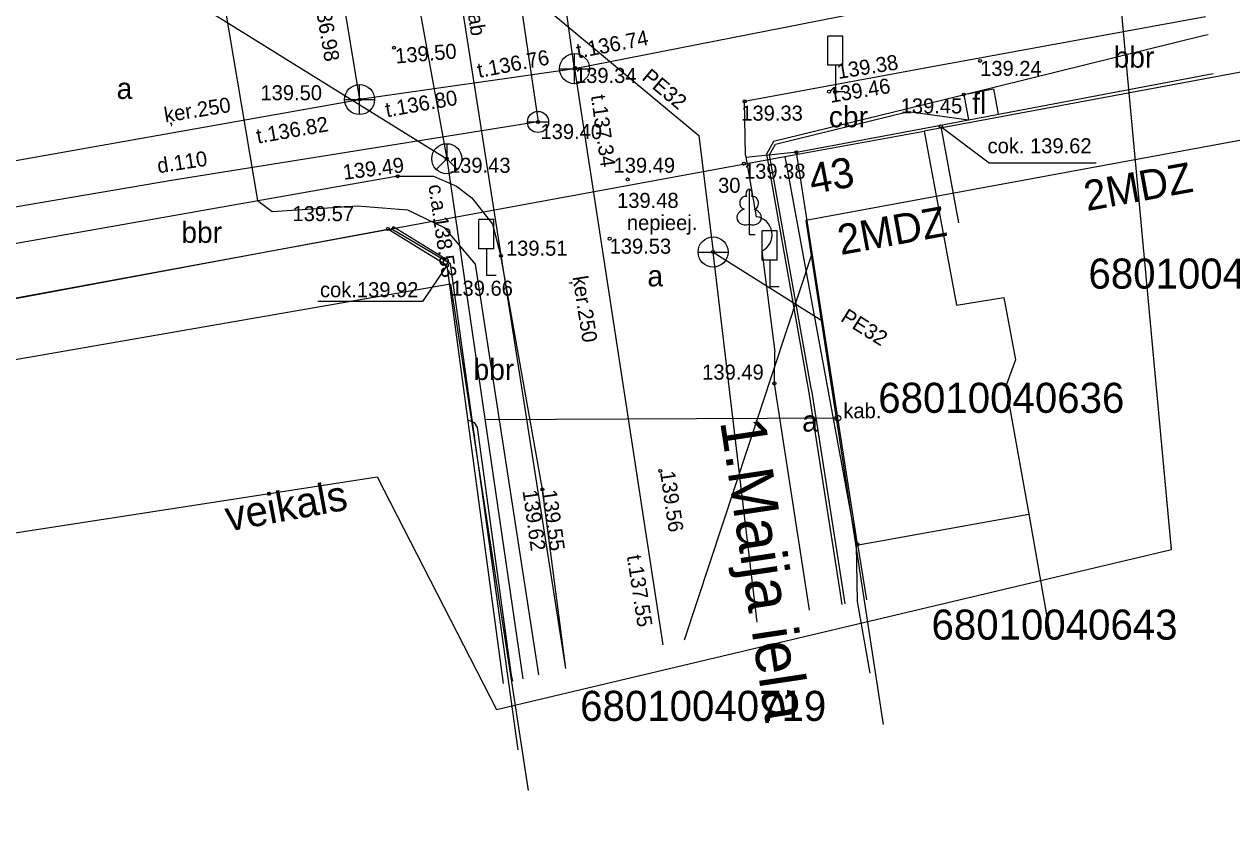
# Model space of a CAD drawing. Extents: x 728492 to 729038, y 272968 to 273171.
# Drawn here: x 728950.66 to 728990.81, y 273100 to 273126.6 of the extents above; entities that cross this region are included whole.
import ezdxf

# ---------------------------------------------------------------- set-up
doc = ezdxf.new("R2010")
doc.units = 0
for name, color, linetype in [('APGR_SARK_####_####_#', 7, 'Continuous'), ('BUVE_BDET_####_####_#', 7, 'Continuous'), ('BUVE_BDET_####_TKST_#', 7, 'Continuous'), ('BUVE_EKAS_####_####_#', 7, 'Continuous'), ('BUVE_EKAS_ADRS_TKST_#', 7, 'Continuous'), ('BUVE_EKAS_BIZM_TKST_#', 7, 'Continuous'), ('BUVE_EKAS_RAKS_TKST_#', 7, 'Continuous'), ('CELI_CAPM_####_####_#', 7, 'Continuous'), ('CELI_CMAL_####_####_#', 7, 'Continuous'), ('CELI_CSEG_####_TKST_#', 7, 'Continuous'), ('CELI_ELEM_####_####_#', 7, 'Continuous'), ('CELI_IELA_####_TKST_#', 7, 'Continuous'), ('ELEK_VADP_ZSPR_####_#', 7, 'Continuous'), ('ELEK_VADV_ZSPR_####_#', 7, 'Continuous'), ('ELEK_VADV_ZSPR_TKST_#', 7, 'Continuous'), ('RAMI_UZMR_####_####_#', 7, 'Continuous'), ('RELJ_AATZ_####_TKST_#', 7, 'Continuous'), ('RELJ_ELEM_####_####_#', 7, 'Continuous'), ('ROBZ_KADS_####_TKST_#', 7, 'Continuous'), ('ROBZ_UZMR_####_####_#', 7, 'Continuous'), ('SAKK_ELEM_####_####_#', 7, 'Continuous'), ('SAKK_ELEM_####_TKST_#', 7, 'Continuous'), ('SAKK_KKAN_####_####_#', 7, 'Continuous'), ('SAKK_KKAN_####_TKST_#', 7, 'Continuous'), ('SAKT_ELEM_####_####_#', 7, 'Continuous'), ('SAKT_VADP_KABE_TKST_#', 7, 'Continuous'), ('SKAN_ELEM_####_####_#', 7, 'Continuous'), ('SKAN_VADP_PAST_####_#', 7, 'Continuous'), ('SKAN_VADP_PAST_TKST_#', 7, 'Continuous'), ('TERT_DIAM_####_TKST_#', 7, 'Continuous'), ('TERT_ELEM_####_####_#', 7, 'Continuous'), ('UDTK_ELEM_####_####_#', 7, 'Continuous'), ('UDTK_ELEM_####_TKST_#', 7, 'Continuous'), ('UDTK_VADP_UDEN_####_#', 7, 'Continuous'), ('UDTK_VADP_UDEN_TKST_#', 7, 'Continuous')]:
    doc.layers.add(name, color=color, linetype=linetype)

msp = doc.modelspace()

# ---------------------------------------------------------------- linework, layer by layer
at = {"layer": 'APGR_SARK_####_####_#'}
for points in [[(728995.336, 273123.524), (728976.642, 273120.075)], [(728976.642, 273120.075), (728979.219, 273103.329)], [(728964.826, 273117.961), (728827.017, 273094.024)], [(728964.826, 273117.961), (728967.415, 273101.144)]]:
    msp.add_lwpolyline(points, dxfattribs=at)
at = {"layer": 'BUVE_BDET_####_####_#'}
for p, q in [((728981.897, 273124.262), (728982.88, 273124.448)), ((728982.88, 273124.448), (728983.039, 273123.607)), ((728981.897, 273124.262), (728982.056, 273123.421)), ((728962.849, 273119.736), (728962.93, 273119.867)), ((728964.653, 273118.806), (728962.93, 273119.867)), ((728964.572, 273118.674), (728964.653, 273118.806))]:
    msp.add_line(p, q, dxfattribs=at)
for points in [[(728981.135, 273123.205), (728982.744, 273121.994), (728986.299, 273121.994)], [(728964.715, 273118.586), (728963.903, 273117.388), (728960.424, 273117.388)]]:
    msp.add_lwpolyline(points, dxfattribs=at)
at = {"layer": 'BUVE_EKAS_####_####_#'}
for p, q in [((728980.838, 273123.191), (728990.19, 273124.959)), ((728976.332, 273122.344), (728980.838, 273123.191)), ((728981.135, 273123.205), (728981.721, 273119.997)), ((728978.36, 273109.32), (728976.332, 273122.344)), ((728941.754, 273115.883), (728962.752, 273119.795)), ((728964.715, 273118.586), (728962.752, 273119.795)), ((728964.715, 273118.586), (728966.582, 273104.697)), ((728978.36, 273109.32), (728978.659, 273107.474))]:
    msp.add_line(p, q, dxfattribs=at)
at = {"layer": 'CELI_CAPM_####_####_#'}
for p, q in [((728989.936, 273126.847), (728980.849, 273125.181)), ((728980.849, 273125.181), (728974.606, 273124.036)), ((728974.642, 273122.247), (728974.606, 273124.036)), ((728974.642, 273122.247), (728974.993, 273120.204)), ((728963.075, 273121.548), (728947.473, 273118.795)), ((728975.187, 273119.075), (728975.614, 273115.713)), ((728975.598, 273114.665), (728975.614, 273115.713))]:
    msp.add_line(p, q, dxfattribs=at)
for points in [[(728963.075, 273121.548), (728964.267, 273121.548), (728965.033, 273121.221), (728965.543, 273120.829), (728966.231, 273119.958), (728966.518, 273118.852)], [(728968.668, 273105.199), (728967.889, 273111.141), (728966.518, 273118.852)], [(728976.768, 273107.128), (728975.598, 273114.665)]]:
    msp.add_lwpolyline(points, dxfattribs=at)
msp.add_arc((728974.919, 273119.605), 0.604, 295.657, 82.7873, dxfattribs=at)
at = {"layer": 'CELI_CMAL_####_####_#'}
msp.add_line((728976.361, 273122.344), (728974.65, 273122.166), dxfattribs=at)
at = {"layer": 'CELI_ELEM_####_####_#'}
for p, q in [((728977.872, 273126.206), (728977.372, 273126.206)), ((728977.372, 273125.237), (728977.372, 273126.206)), ((728977.872, 273125.237), (728977.872, 273126.206)), ((728977.872, 273125.237), (728977.372, 273125.237)), ((728977.626, 273125.237), (728977.626, 273124.359)), ((728977.626, 273124.359), (728977.941, 273124.359)), ((728966.277, 273120.106), (728965.777, 273120.106)), ((728965.777, 273119.137), (728965.777, 273120.106)), ((728966.277, 273119.137), (728966.277, 273120.106)), ((728975.689, 273119.73), (728975.189, 273119.73)), ((728975.189, 273118.761), (728975.189, 273119.73)), ((728975.689, 273118.761), (728975.689, 273119.73)), ((728966.277, 273119.137), (728965.777, 273119.137)), ((728966.031, 273119.137), (728966.031, 273118.259)), ((728975.689, 273118.761), (728975.189, 273118.761)), ((728975.443, 273118.761), (728975.443, 273117.883)), ((728966.031, 273118.259), (728966.346, 273118.259)), ((728975.443, 273117.883), (728975.758, 273117.883))]:
    msp.add_line(p, q, dxfattribs=at)
at = {"layer": 'ELEK_VADP_ZSPR_####_#'}
for points in [[(728951.576, 273130.701), (728955.714, 273131.287), (728956.029, 273131.332), (728956.659, 273131.106), (728958.413, 273120.742), (728958.908, 273120.382), (728961.741, 273120.562), (728963.406, 273120.427), (728964.62, 273119.841), (728965.655, 273118.625), (728967.754, 273104.979)], [(728990.017, 273126.246), (728989.901, 273126.224), (728984.022, 273124.771), (728980.928, 273124.012)], [(728980.928, 273124.012), (728975.567, 273122.698), (728975.335, 273122.276), (728976.734, 273114.424)], [(728976.832, 273114.442), (728975.44, 273122.259), (728975.633, 273122.611), (728980.059, 273123.696), (728982.056, 273123.421)], [(728976.734, 273114.424), (728977.762, 273107.832), (728977.842, 273107.324)], [(728976.833, 273114.439), (728977.861, 273107.848), (728977.941, 273107.342)], [(728965.405, 273113.452), (728965.613, 273113.368), (728965.715, 273113.206), (728966.852, 273104.973), (728966.889, 273104.771)]]:
    msp.add_lwpolyline(points, dxfattribs=at)
at = {"layer": 'ELEK_VADV_ZSPR_####_#'}
for p, q in [((728964.384, 273132.474), (728968.655, 273105.196)), ((728972.606, 273106.148), (728976.856, 273118.978))]:
    msp.add_line(p, q, dxfattribs=at)
at = {"layer": 'RAMI_UZMR_####_####_#'}
msp.add_lwpolyline([(728688.721, 273058.407), (728702.149, 273066.922), (728733.452, 273072.937), (728813.127, 273088.247), (728815.181, 273072.879), (728831.342, 273076.994), (728831.817, 273091.35), (728930.137, 273106.573), (728962.389, 273111.567), (728966.363, 273103.835), (728988.796, 273109.153), (728985.811, 273141.417), (728955.146, 273144.603), (728957.616, 273137.975), (728904.333, 273130.641), (728847.677, 273120.095), (728823.483, 273119.793), (728790.036, 273112.558), (728726.814, 273102.175), (728686.914, 273096.216)], dxfattribs=at)
at = {"layer": 'RELJ_ELEM_####_####_#'}
for centre, radius in [((728962.956, 273125.816), 0.05), ((728968.957, 273125.121), 0.05), ((728968.971, 273125.146), 0.05), ((728982.44, 273125.381), 0.05), ((728977.415, 273124.357), 0.05), ((728977.622, 273124.351), 0.0534), ((728981.897, 273124.262), 0.05), ((728961.809, 273124.096), 0.05), ((728974.606, 273124.036), 0.05), ((728967.741, 273123.352), 0.05), ((728981.135, 273123.205), 0.0534), ((728976.332, 273122.344), 0.05), ((728964.707, 273122.13), 0.05), ((728974.588, 273121.964), 0.05), ((728963.075, 273121.548), 0.05), ((728970.717, 273121.441), 0.05), ((728962.752, 273119.795), 0.0534), ((728962.752, 273119.795), 0.05), ((728970.122, 273119.474), 0.05), ((728973.561, 273119.03), 0.0534), ((728964.635, 273118.794), 0.05), ((728966.507, 273118.907), 0.05), ((728964.715, 273118.586), 0.0534), ((728964.715, 273118.586), 0.05), ((728975.598, 273114.665), 0.0534), ((728971.802, 273111.76), 0.05), ((728967.889, 273111.141), 0.05), ((728978.36, 273109.32), 0.05)]:
    msp.add_circle(centre, radius, dxfattribs=at)
at = {"layer": 'ROBZ_UZMR_####_####_#'}
for p, q in [((728992.588, 273125.277), (728980.575, 273123.044)), ((728975.951, 273122.201), (728980.575, 273123.044)), ((728980.575, 273123.044), (728981.651, 273117.263)), ((728962.863, 273119.799), (728975.951, 273122.201)), ((728975.951, 273122.201), (728978.324, 273109.297)), ((728929.443, 273113.665), (728962.863, 273119.799)), ((728964.835, 273118.634), (728962.863, 273119.799)), ((728967.08, 273102.487), (728964.835, 273118.634)), ((728981.651, 273117.263), (728983.231, 273117.517)), ((728983.231, 273117.517), (728983.613, 273115.452)), ((728983.613, 273115.452), (728983.288, 273114.57)), ((728983.288, 273114.57), (728984.06, 273110.318)), ((728978.324, 273109.297), (728984.06, 273110.318)), ((728984.06, 273110.318), (728984.751, 273106.345)), ((728978.366, 273107.416), (728978.324, 273109.297)), ((728978.784, 273105.042), (728978.366, 273107.416))]:
    msp.add_line(p, q, dxfattribs=at)
at = {"layer": 'SAKK_ELEM_####_####_#'}
msp.add_line((728964.707, 273122.13), (728965.061, 273121.776), dxfattribs=at)
msp.add_lwpolyline([(728964.707, 273122.63), (728964.707, 273122.13), (728964.354, 273121.776)], dxfattribs=at)
msp.add_circle((728964.707, 273122.13), 0.5, dxfattribs=at)
at = {"layer": 'SAKK_KKAN_####_####_#'}
msp.add_line((728977.707, 273113.51), (728965.978, 273113.455), dxfattribs=at)
for points in [[(728963.132, 273130.774), (728964.707, 273122.13)], [(728953.432, 273129.137), (728964.707, 273122.13)], [(728964.707, 273122.13), (728967.239, 273104.855)]]:
    msp.add_lwpolyline(points, dxfattribs=at)
at = {"layer": 'SAKT_ELEM_####_####_#'}
msp.add_circle((728977.707, 273113.51), 0.1, dxfattribs=at)
at = {"layer": 'SKAN_ELEM_####_####_#'}
for p, q in [((728968.957, 273124.621), (728968.957, 273125.621)), ((728968.457, 273125.121), (728969.457, 273125.121)), ((728961.809, 273123.596), (728961.809, 273124.596)), ((728961.309, 273124.096), (728962.309, 273124.096))]:
    msp.add_line(p, q, dxfattribs=at)
for centre in [(728968.957, 273125.121), (728961.809, 273124.096)]:
    msp.add_circle(centre, 0.5, dxfattribs=at)
at = {"layer": 'SKAN_VADP_PAST_####_#'}
for points in [[(728968.957, 273125.121), (728966.415, 273143.211)], [(728958.775, 273142.509), (728961.809, 273124.096)], [(728980.586, 273127.408), (728968.957, 273125.121)], [(728968.957, 273125.121), (728961.809, 273124.096)], [(728968.957, 273125.121), (728971.891, 273105.976)], [(728926.111, 273118.506), (728946.06, 273121.302), (728961.809, 273124.096)]]:
    msp.add_lwpolyline(points, dxfattribs=at)
at = {"layer": 'TERT_ELEM_####_####_#'}
for p, q in [((728974.759, 273119.956), (728974.759, 273119.609)), ((728974.759, 273119.609), (728974.959, 273119.609))]:
    msp.add_line(p, q, dxfattribs=at)
for points in [[(728974.759, 273121.109), (728974.759, 273119.956)], [(728974.849, 273120.877), (728974.848, 273120.878)]]:
    msp.add_lwpolyline(points, dxfattribs=at)
for centre, major_axis, ratio, start_param, end_param in [((728974.759, 273120.959), (0, -0.15), 0.707107, 3.14537, 5.287485), ((728974.759, 273120.959), (0, -0.15), 0.707107, 0.995701, 3.137816), ((728974.631, 273120.665), (-0.039, -0.212), 0.861323, 3.141593, 6.283185), ((728974.887, 273120.665), (0.039, -0.212), 0.861323, 0, 3.141593), ((728974.669, 273120.202), (0.307, 0.095), 0.814445, 1.570796, 4.752015), ((728974.849, 273120.202), (-0.307, 0.095), 0.814445, 1.531171, 4.712389)]:
    msp.add_ellipse(centre, major_axis=major_axis, ratio=ratio, start_param=start_param, end_param=end_param, dxfattribs=at)
at = {"layer": 'UDTK_ELEM_####_####_#'}
for p, q in [((728967.389, 273123.352), (728968.092, 273123.352)), ((728967.74, 273123.352), (728967.74, 273123.353)), ((728973.06, 273119.03), (728974.06, 273119.03))]:
    msp.add_line(p, q, dxfattribs=at)
for centre, radius in [((728967.741, 273123.352), 0.351), ((728973.561, 273119.03), 0.5)]:
    msp.add_circle(centre, radius, dxfattribs=at)
at = {"layer": 'UDTK_VADP_UDEN_####_#'}
for p, q in [((728967.08, 273127.91), (728967.741, 273123.352)), ((728967.741, 273123.352), (728955.625, 273121.419)), ((728955.625, 273121.419), (728923.344, 273115.945)), ((728975.029, 273106.732), (728973.561, 273119.03))]:
    msp.add_line(p, q, dxfattribs=at)
for points in [[(728967.08, 273127.91), (728973.084, 273122.906), (728973.569, 273119.035)], [(728973.561, 273119.03), (728977.205, 273116.735)]]:
    msp.add_lwpolyline(points, dxfattribs=at)

# ---------------------------------------------------------------- texts
at = {"layer": 'BUVE_BDET_####_TKST_#'}
for s, height, p in [('fl', 0.7, (728982.174, 273123.618)), ('cok. 139.62', 0.5, (728982.687, 273122.31)), ('cok.139.92', 0.5, (728960.494, 273117.529))]:
    msp.add_text(s, height=height, dxfattribs=at).set_placement(p)
at = {"layer": 'BUVE_EKAS_ADRS_TKST_#'}
msp.add_text('43', height=1, rotation=10.7088, dxfattribs=at).set_placement((728976.852, 273120.948))
at = {"layer": 'BUVE_EKAS_BIZM_TKST_#'}
msp.add_text('veikals', height=1, rotation=10.4482, dxfattribs=at).set_placement((728957.442, 273109.741))
at = {"layer": 'BUVE_EKAS_RAKS_TKST_#'}
for p in [(728985.988, 273120.387), (728977.803, 273118.927)]:
    msp.add_text('2MDZ', height=1, rotation=10.3483, dxfattribs=at).set_placement(p)
at = {"layer": 'CELI_CSEG_####_TKST_#'}
for s, p in [('bbr', (728986.877, 273125.155)), ('a', (728953.731, 273124.117)), ('cbr', (728977.41, 273123.174)), ('bbr', (728955.884, 273119.334)), ('a', (728971.378, 273117.889)), ('bbr', (728965.599, 273114.778)), ('a', (728976.523, 273113.065))]:
    msp.add_text(s, height=0.7, dxfattribs=at).set_placement(p)
at = {"layer": 'CELI_IELA_####_TKST_#'}
msp.add_text('1.Maija iela', height=1.5, rotation=278.5972, dxfattribs=at).set_placement((728973.79, 273113.408))
at = {"layer": 'ELEK_VADV_ZSPR_TKST_#'}
msp.add_text('kab', height=0.5, rotation=278.8998, dxfattribs=at).set_placement((728965.354, 273127.247))
at = {"layer": 'RELJ_AATZ_####_TKST_#'}
for s, rotation, p in [('139.50', 4.8489, (728963.015, 273125.291)), ('139.38', 9.1698, (728977.727, 273124.776)), (' 139.46', 9.47, (728977.286, 273123.954)), ('139.49', 7.2233, (728961.284, 273121.428)), ('139.56', 278.3371, (728971.796, 273111.721)), ('139.62', 277.991, (728967.225, 273111.098)), ('139.55', 277.991, (728967.862, 273111.098))]:
    msp.add_text(s, height=0.5, rotation=rotation, dxfattribs=at).set_placement(p)
for s, p in [('139.24', (728982.44, 273124.881)), ('139.33', (728974.499, 273123.394)), (' 139.45', (728979.612, 273123.634)), (' 139.49', (728970.067, 273121.663)), ('139.38', (728974.588, 273121.464)), (' 139.57', (728959.393, 273120.056)), ('139.53', (728970.122, 273118.974)), (' 139.51', (728966.49, 273118.908)), (' 139.66', (728964.674, 273117.578)), ('139.49', (728973.2, 273114.79))]:
    msp.add_text(s, height=0.5, dxfattribs=at).set_placement(p)
at = {"layer": 'ROBZ_KADS_####_TKST_#'}
for s, p in [('68010040637', (728986.039, 273117.814)), ('68010040636', (728979.053, 273113.687)), ('68010040643', (728980.822, 273106.152)), ('68010040719', (728969.142, 273103.453))]:
    msp.add_text(s, height=1, dxfattribs=at).set_placement(p)
at = {"layer": 'SAKK_ELEM_####_TKST_#'}
msp.add_text('139.43', height=0.5, dxfattribs=at).set_placement((728964.782, 273121.662))
at = {"layer": 'SAKK_KKAN_####_TKST_#'}
msp.add_text('c.a.138.53', height=0.5, rotation=278.3397, dxfattribs=at).set_placement((728964.094, 273121.243))
at = {"layer": 'SAKT_VADP_KABE_TKST_#'}
msp.add_text(' kab.', height=0.5, dxfattribs=at).set_placement((728977.707, 273113.51))
at = {"layer": 'SKAN_ELEM_####_####_#'}
for s, p in [('139.34', (728968.971, 273124.646)), ('139.50', (728958.514, 273124.073))]:
    msp.add_text(s, height=0.5, dxfattribs=at).set_placement(p)
at = {"layer": 'SKAN_VADP_PAST_TKST_#'}
for s, rotation, p in [('t.136.98', 279.7272, (728960.25, 273127.71)), ('t.136.74', 10.8573, (728969.068, 273125.461)), ('t.136.76', 10.8573, (728965.773, 273124.812)), ('t.136.80', 10.0558, (728962.713, 273123.504)), ('ķer.250', 9.1742, (728955.352, 273123.332)), ('t.137.34', 277.9522, (728969.497, 273124.22)), ('t.136.82', 10.0558, (728958.423, 273122.628)), ('ķer.250', 278.8329, (728968.886, 273118.2)), ('t.137.55', 278.715, (728970.692, 273108.932))]:
    msp.add_text(s, height=0.5, rotation=rotation, dxfattribs=at).set_placement(p)
at = {"layer": 'TERT_DIAM_####_TKST_#'}
msp.add_text('30', height=0.5, dxfattribs=at).set_placement((728973.727, 273120.997))
at = {"layer": 'UDTK_ELEM_####_TKST_#'}
for s, p in [('139.40', (728967.824, 273122.783)), (' 139.48', (728970.184, 273120.496)), ('nepieej.', (728970.696, 273119.757))]:
    msp.add_text(s, height=0.5, dxfattribs=at).set_placement(p)
at = {"layer": 'UDTK_VADP_UDEN_TKST_#'}
for s, rotation, p in [('PE32', 320.1907, (728971.162, 273124.778)), ('d.110', 8.8654, (728955.121, 273121.644)), ('PE32', 327.8091, (728977.768, 273116.756))]:
    msp.add_text(s, height=0.5, rotation=rotation, dxfattribs=at).set_placement(p)

doc.saveas('drawing.dxf')
